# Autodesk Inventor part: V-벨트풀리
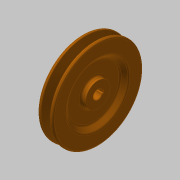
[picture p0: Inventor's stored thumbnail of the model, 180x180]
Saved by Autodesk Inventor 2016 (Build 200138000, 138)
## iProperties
Created: 2015-12
Part Number: V-벨트풀리
Document SubType Name: Modeling
Designer: mdu
Density: 8.08 g/cm^3
Material: 스테인리스강
Appearance: 주황색
Mass: 1135.6 g
Surface Area: 369.424 cm^2
Volume: 140.544 cm^3
Author: mdu
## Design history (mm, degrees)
sketch "스케치1"
  geometry: L1 (-10, 0)-(10, 0); L2 (-10, 0)-(-10, 16); L3 (-10, 16)-(-4, 16); L4 (-4, 16)-(-4, 35); L5 (-4, 35)-(-10, 41); L6 (-10, 41)-(-10, 59.5); L7 (-10, 59.5)-(-6.062, 59.5); L8 (-6.062, 59.5)-(-2.001, 47); L9 (-2.001, 47)-(2.001, 47); L10 (2.001, 47)-(6.062, 59.5); L11 (6.062, 59.5)-(10, 59.5); L12 (10, 59.5)-(10, 41); L13 (10, 41)-(4, 35); L14 (4, 35)-(4, 16); L15 (4, 16)-(10, 16); L16 (10, 16)-(10, 0); L17 (-4.6, 55)-(4.6, 55); 2 further points
  constraints: 34 end point, 7 parallel, 6 equal length, 5 collinear, 3 perpendicular, 2 point on line, 1 coincident, 1 horizontal, 1 midpoint
  dimensions: "d0" = 20 distance of L1.start L1.end; "d1" = 9.2 distance of L17.start L17.end; "d2" = 36 deg angle of L10 L8; "d3" = 4.5 distance between parallel lines of L7 L17; "d4" = 8 distance between parallel lines of L9 L17; "d6" = 110 diameter of L17 L1; "d7" = 32 diameter of L3 L1; "d8" = 82 diameter of L5.end L1; "d9" = 6 distance of L2.end L3.end; "d10" = 135 deg angle of L4 L5
revolve "회전1" sketch "스케치1" stored, may be unused: angle "d11" = 90 deg
fillet "모깎기1" dims "d12" = 2, "d13" = 0.5, "d14" = 1, "d15" = 3
sketch "스케치2"
  geometry: L1 (-2, 5.657)-(-2, 7.8); L2 (-2, 7.8)-(2, 7.8); L3 (2, 7.8)-(2, 5.657); A1 r 6 centre (0, 0) between (-2, 5.657) and (2, 5.657); 1 further point
  constraints: 6 end point, 2 parallel, 2 point on circle, 1 centre point, 1 coincident, 1 perpendicular, 1 vertical
  dimensions: "d16" = 12 diameter of A1; "d17" = 4 distance of L1.end L2.end; "d18" = 13.8 dimension on A1 L2 (computed from d16)
extrude "돌출1" cut sketch "스케치2" stored distance "d19" = 10; taper "d20" = 0 deg
chamfer "모따기2" distance "d24" = 0.5; stored, may be unused: second distance "d25" = 2, angle "d26" = 45 deg
sketch "스케치3" dims "d27" = 100
  geometry: C1 r 2.5 at (0, 50); 2 further points
  constraints: 2 vertical alignment, 1 centre point, 1 coincident, 2 other
  dimensions: "d28" = 5 diameter of C1
extrude "돌출2" join sketch "스케치3" distance "d29" = 1; taper "d30" = 0 deg
node "솔리드1"
